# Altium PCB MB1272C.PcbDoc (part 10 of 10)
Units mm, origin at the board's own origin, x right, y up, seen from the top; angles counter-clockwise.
Board outline 101 x 71 mm, 6 copper layers (Top Layer, Signal Layer 1, Signal Layer 2, Signal Layer 3, Signal Layer 4, Bottom Layer), stack 1.552 mm thick; 520 components, 478 nets, 2156 pads, 1894 vias.
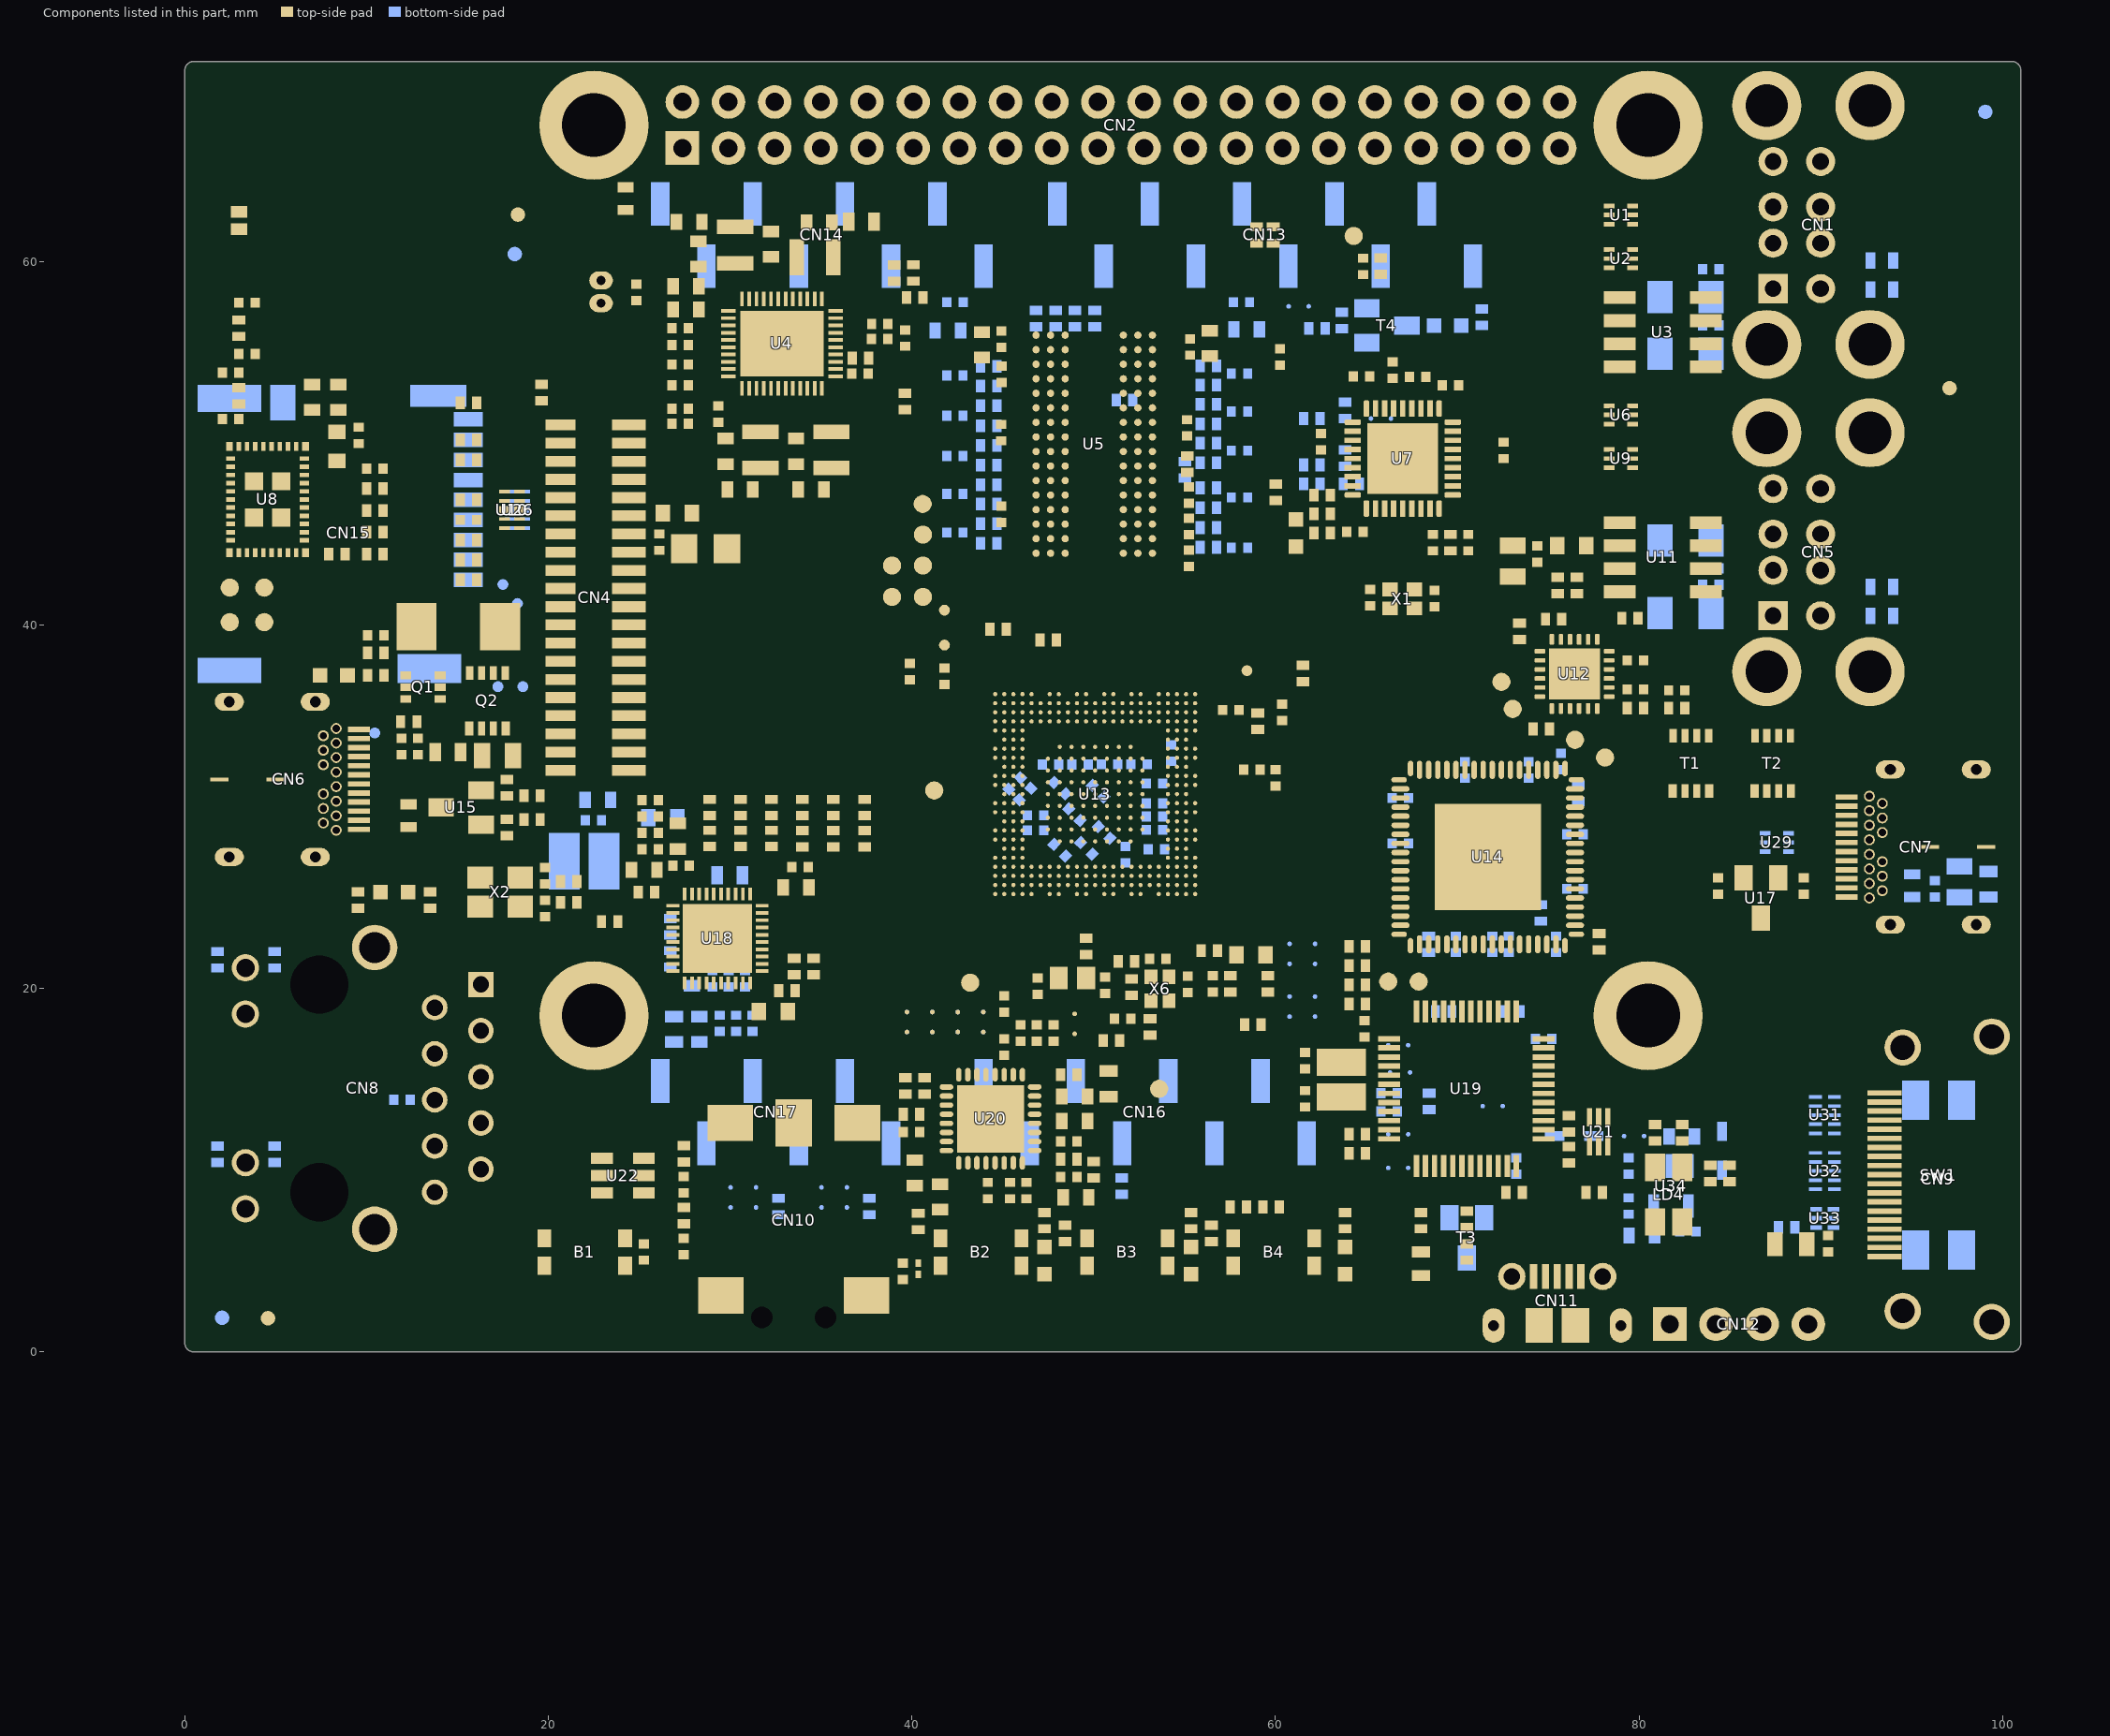
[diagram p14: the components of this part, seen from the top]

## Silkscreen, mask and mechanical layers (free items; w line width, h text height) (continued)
Drill Drawing:
  drawing of 549 lines, arcs and shapes, not listed
  text "PCB SPECIFICATIONS :" at 6.92,173.965 h3
  text "PCB : TYPE 4" at 155.276,173.613 h3
  text "MINIMUN PARAMETERS" at 192.17,173.59 h3
  text "A.   MATERIAL :" at 6.92,169.965 h3
  text "FR-4" at 45.42,169.965 h3
  text "TG-170" at 61.92,169.965 h3
  text "X  TG-150" at 80.17,169.965 h3
  text "TG-140" at 96.17,169.965 h3
  text "ASPECT-RATIO, AXE Z :" at 155.276,168.113 h3
  text "DEFAULT" at 192.17,168.09 h3
  text "B.   MATERIAL FAMILY :" at 6.92,166.965 h3
  text "N/A" at 45.42,166.965 h3
  text "C.   SOLDERMASK COLOR :" at 6.92,163.965 h3
  text "X  BLUE" at 45.42,163.965 h3
  text "WHITE" at 61.92,163.965 h3
  text "RED" at 80.17,163.965 h3
  text "BLACK" at 96.17,163.965 h3
  text "TRACKS : 0.090mm           / GAPS : 0.090mm" at 192.17,162.34 h3
  text "6:1 to 8:1 / LEVEL \"B\"" at 155.295,161.365 h3
  text "D.   SILKSCREEN COLOR :" at 6.92,160.965 h3
  text "X  WHITE" at 45.42,160.965 h3
  text "YELLOW" at 61.92,160.965 h3
  text "BLACK" at 80.17,160.965 h3
  text "Blue ink PANTONE 2955" at 96.17,160.965 h3
  text "MCU" at 192.495,158.265 h3
  text "E.   SURFACE FINISH :" at 6.92,157.965 h3
  text "X  ENIG" at 45.42,157.965 h3
  text "IMMERSION SILVER" at 61.92,157.965 h3
  text "IMMERSION TIN" at 96.17,157.965 h3
  text "HASL" at 45.42,154.965 h3
  text "HASL (PB-FREE)" at 61.92,154.965 h3
  text "GOLDEN FINGER" at 96.17,154.965 h3
  text "TRACKS : 0.090mm           / GAPS : 0.080mm" at 192.495,152.515 h3
  text "F.   IMPEDANCE CONTROL :" at 6.92,151.965 h3
  text "NO" at 45.42,151.965 h3
  text "X  YES  (SEE IMPEDANCE TABLE FOR DETAIL INFORMATION)" at 61.92,151.965 h3
  text "G.   THROUGH VIA :" at 6.92,148.965 h3
  text "PLUG THE VIAS WHICH ARE COVERED WITH SOLDERMASK ONE OR TWO SIDE." at 45.42,148.965 h3
  text "PLUG MATERIAL :" at 45.42,145.965 h3
  text "X  SOLDERMASK" at 70.92,145.965 h3
  text "NON-CONDUCTIVE EPOXY." at 96.17,145.965 h3
  text "H.   STACK-UP :" at 6.92,142.965 h3
  text "SEE LAYER STACK-UP SEQUENCE FOR OVERALL THICKNESS." at 45.42,142.965 h3
  text "Layer" at 157.322,132.1 h2
  text "Name" at 165.69,132.1 h2
  text "Material" at 181.866,132.1 h2
  text "Thickness" at 198.133,132.1 h2
  text "Constant" at 210.074,132.1 h2
  text "Board Layer Stack" at 221.128,132.1 h2
  text "IMPEDANCE TABLE     SDMMC1" at 63.325,131.975 h3
  text "IMPEDANCE TABLE     DDR" at -28.85,131.95 h3
  text "1" at 157.322,128.1 h2
  text "Top Overlay" at 165.69,128.1 h2
  text "LAYER" at -23.9,127 h3
  text "LAYER" at 67.575,126.975 h3
  text "TRACE" at 83.825,126.975 h3
  text "SPACING" at 94.325,126.975 h3
  text "IMPEDANCE" at 107.825,126.975 h3
  text "IMPEDANCE" at 124.825,126.975 h3
  text "TOL." at 143.575,126.975 h3
  text "TRACE" at -8.35,126.95 h3
  text "SPACING" at 2.15,126.95 h3
  text "IMPEDANCE" at 15.65,126.95 h3
  text "IMPEDANCE" at 32.65,126.95 h3
  text "TOL." at 51.4,126.95 h3
  text "(mm)" at 97.65,124.5 h2.5
  text "(mm)" at 5.475,124.475 h2.5
  text "(mm)" at 85.825,124.45 h2.5
  text "(mm)" at -6.35,124.425 h2.5
  text "(Single ended)" at 108.325,124.225 h2.5
  text "(Differential)" at 126.075,124.225 h2.5
  text "(Single ended)" at 16.15,124.2 h2.5
  text "(Differential)" at 33.9,124.2 h2.5
  text "2" at 157.322,124.1 h2
  text "Top Solder" at 165.69,124.1 h2
  text "Solder Resist" at 181.866,124.1 h2
  text "0,020mm" at 198.133,124.1 h2
  text "3,5" at 210.074,124.1 h2
  text "+/- 15%" at 142.63,120.585 h3
  text "0.130" at 84.8,120.5 h3
  text "0.120" at -7.375,120.475 h3
  text "0.260" at 96.825,120.475 h3
  text "0.300" at 4.65,120.45 h3
  text "+/- 10%" at 49.825,120.45 h3
  text "TOP/BOTTOM" at 63.805,120.46 h3
  text "50 ohm" at 111.18,120.41 h3
  text "55 ohm" at 19.005,120.385 h3
  text "NA" at 130.73,120.36 h3
  text "NA" at 38.555,120.335 h3
  text "3" at 157.322,120.1 h2
  text "Top Layer" at 165.69,120.1 h2
  text "Copper" at 181.866,120.1 h2
  text "0,035mm" at 198.133,120.1 h2
  text "TOP" at -22.075,118.825 h3
  text "+/- 15%" at 142.635,117.07 h3
  text "+/- 10%" at 49.85,117.05 h3
  text "NA" at 21.075,117 h3
  text "0.130" at 84.805,116.985 h3
  text "0.260" at 96.83,116.96 h3
  text "LAYER 2" at 67.25,116.925 h3
  text "100 ohm" at 35.05,116.9 h3
  text "50 ohm" at 111.185,116.895 h3
  text "NA" at 130.735,116.845 h3
  text "0.100/0.130/0.100" at -7.825,116.775 h3
  text "4" at 157.322,116.1 h2
  text "Dielectric 1" at 165.69,116.1 h2
  text "IT-180A 3313H" at 181.866,116.1 h2
  text "0,099mm" at 198.133,116.1 h2
  text "4,2" at 210.074,116.1 h2
  text "0.127" at -7.38,113.465 h3
  text "0.300" at 4.645,113.44 h3
  text "+/- 10%" at 49.82,113.44 h3
  text "55 ohm" at 19,113.375 h3
  text "NA" at 38.55,113.325 h3
  text "5" at 157.322,112.1 h2
  text "Signal Layer 1" at 165.69,112.1 h2
  text "Copper" at 181.866,112.1 h2
  text "0,035mm" at 198.133,112.1 h2
  text "LAYER 2" at -25.2,111.825 h3
  text "+/- 10%" at 49.845,110.04 h3
  text "NA" at 21.07,109.99 h3
  text "100 ohm" at 35.045,109.89 h3
  text "IMPEDANCE TABLE     USB" at 63.175,109.875 h3
  text "0.090/0.140/0.090" at -7.83,109.765 h3
  text "6" at 157.322,108.1 h2
  text "Dielectric 2" at 165.69,108.1 h2
  text "IT-180A" at 181.866,108.1 h2
  text "0,130mm" at 198.133,108.1 h2
  text "4,2" at 210.074,108.1 h2
  text "0.120" at -7.38,106.44 h3
  text "0.300" at 4.645,106.415 h3
  text "+/- 10%" at 49.82,106.415 h3
  text "55 ohm" at 19,106.35 h3
  text "NA" at 38.55,106.3 h3
  text "LAYER" at 67.425,104.875 h3
  text "TRACE" at 83.675,104.875 h3
  text "SPACING" at 94.175,104.875 h3
  text "IMPEDANCE" at 107.675,104.875 h3
  text "IMPEDANCE" at 124.675,104.875 h3
  text "TOL." at 143.425,104.875 h3
  text "BOTTOM" at -24.775,104.75 h3
  text "7" at 157.322,104.1 h2
  text "Signal Layer 2" at 165.69,104.1 h2
  text "Copper" at 181.866,104.1 h2
  text "0,035mm" at 198.133,104.1 h2
  text "+/- 10%" at 49.845,103.015 h3
  text "NA" at 21.07,102.965 h3
  text "100 ohm" at 35.045,102.865 h3
  text "0.100/0.130/0.100" at -7.83,102.74 h3
  text "(mm)" at 97.5,102.4 h2.5
  text "(mm)" at 85.675,102.35 h2.5
  text "(Single ended)" at 108.175,102.125 h2.5
  text "(Differential)" at 125.925,102.125 h2.5
  text "8" at 157.322,100.1 h2
  text "Dielectric 3" at 165.69,100.1 h2
  text "IT-180A 1080*2" at 181.866,100.1 h2
  text "0,885mm" at 198.133,100.1 h2
  text "4,25" at 210.074,100.1 h2
  text "0.100" at 84.65,98.4 h3
  text "NA" at 113.275,98.4 h3
  text "0.090" at 96.675,98.375 h3
  text "90 ohm" at 127.925,98.375 h3
  text "+/- 15%" at 141.925,98.375 h3
  text "TOP/BOTTOM" at 63.655,98.36 h3
  text "9" at 157.322,96.1 h2
  text "Signal Layer 3" at 165.69,96.1 h2
  text "Copper" at 181.866,96.1 h2
  text "0,035mm" at 198.133,96.1 h2
  text "IMPEDANCE TABLE     DSI" at 63.175,92.475 h3
  text "10" at 157.322,92.1 h2
  text "Dielectric 4" at 165.69,92.1 h2
  text "IT-180A" at 181.866,92.1 h2
  text "0,130mm" at 198.133,92.1 h2
  text "4,2" at 210.074,92.1 h2
  text "11" at 157.322,88.1 h2
  text "Signal Layer 4" at 165.69,88.1 h2
  text "Copper" at 181.866,88.1 h2
  text "0,035mm" at 198.133,88.1 h2
  text "LAYER" at 67.425,87.475 h3
  text "TRACE" at 83.675,87.475 h3
  text "SPACING" at 94.175,87.475 h3
  text "IMPEDANCE" at 107.675,87.475 h3
  text "IMPEDANCE" at 124.675,87.475 h3
  text "TOL." at 143.425,87.475 h3
  text "(mm)" at 97.5,85 h2.5
  text "(mm)" at 85.675,84.95 h2.5
  text "(Single ended)" at 108.175,84.725 h2.5
  text "(Differential)" at 125.925,84.725 h2.5
  text "12" at 157.322,84.1 h2
  text "Dielectric 5" at 165.69,84.1 h2
  text "IT-180A 3313H" at 181.866,84.1 h2
  text "0,099mm" at 198.133,84.1 h2
  text "4,2" at 210.074,84.1 h2
  text "0.100" at 84.65,81 h3
  text "NA" at 113.275,81 h3
  text "0.130" at 96.675,80.975 h3
  text "100 ohm" at 127.925,80.975 h3
  text "+/- 15%" at 141.925,80.975 h3
  text "TOP/BOTTOM" at 63.655,80.96 h3
  text "13" at 157.322,80.1 h2
  text "Bottom Layer" at 165.69,80.1 h2
  text "Copper" at 181.866,80.1 h2
  text "0,035mm" at 198.133,80.1 h2
  text "14" at 157.322,76.1 h2
  text "Bottom Solder" at 165.69,76.1 h2
  text "Solder Resist" at 181.866,76.1 h2
  text "0,020mm" at 198.133,76.1 h2
  text "3,5" at 210.074,76.1 h2
  text "15" at 157.322,72.1 h2
  text "Bottom Overlay" at 165.69,72.1 h2
  text "Symbol" at 114.772,63.867 h2.4
  text "Count" at 124.175,63.867 h2.4
  text "Hole Size" at 134.939,63.867 h2.4
  text "Plated" at 154.189,63.867 h2.4
  text "Hole Type" at 162.444,63.867 h2.4
  text "Drill Layer Pair" at 174.458,63.867 h2.4
  text "Hole Length" at 197.658,63.867 h2.4
  text "Routed Path Length" at 215.794,63.867 h2.4
  text "530" at 124.175,59.722 h2
  text "0,100mm (3,94mil)" at 134.939,59.722 h2
  text "PTH" at 154.189,59.722 h2
  text "Round" at 162.444,59.722 h2
  text "Top Layer - Signal Layer 1" at 174.458,59.722 h2
  text "-" at 197.658,59.722 h2
  text "-" at 215.794,59.722 h2
  text "O" at 113.984,59.468 h1.84
  text "912" at 124.175,55.577 h2
  text "0,200mm (7,87mil)" at 134.939,55.577 h2
  text "PTH" at 154.189,55.577 h2
  text "Round" at 162.444,55.577 h2
  text "Top Layer - Bottom Layer" at 174.458,55.577 h2
  text "-" at 197.658,55.577 h2
  text "-" at 215.794,55.577 h2
  text "452" at 124.175,51.431 h2
  text "0,300mm (11,81mil)" at 134.939,51.431 h2
  text "PTH" at 154.189,51.431 h2
  text "Round" at 162.444,51.431 h2
  text "Top Layer - Bottom Layer" at 174.458,51.431 h2
  text "-" at 197.658,51.431 h2
  text "-" at 215.794,51.431 h2
  text "28" at 124.175,47.286 h2
  text "0,400mm (15,75mil)" at 134.939,47.286 h2
  text "PTH" at 154.189,47.286 h2
  text "Round" at 162.444,47.286 h2
  text "Top Layer - Bottom Layer" at 174.458,47.286 h2
  text "-" at 197.658,47.286 h2
  text "-" at 215.794,47.286 h2
  text "I" at 114.291,47.032 h1.84
  text "2" at 124.175,43.141 h2
  text "0,500mm (19,69mil)" at 134.939,43.141 h2
  text "PTH" at 154.189,43.141 h2
  text "Round" at 162.444,43.141 h2
  text "Top Layer - Bottom Layer" at 174.458,43.141 h2
  text "-" at 197.658,43.141 h2
  text "-" at 215.794,43.141 h2
  text "J" at 113.984,42.887 h1.84
  text "8" at 124.175,38.996 h2
  text "0,600mm (23,62mil)" at 134.939,38.996 h2
  text "PTH" at 154.189,38.996 h2
  text "Slot" at 162.444,38.996 h2
  text "Top Layer - Bottom Layer" at 174.458,38.996 h2
  text "1,200mm (47,24mil)" at 197.658,38.996 h2
  text "0,600mm (23,62mil)" at 215.794,38.996 h2
  text "H" at 113.984,38.742 h1.84
  text "2" at 124.175,34.85 h2
  text "0,600mm (23,62mil)" at 134.939,34.85 h2
  text "PTH" at 154.189,34.85 h2
  text "Slot" at 162.444,34.85 h2
  text "Top Layer - Bottom Layer" at 174.458,34.85 h2
  text "1,300mm (51,18mil)" at 197.658,34.85 h2
  text "0,700mm (27,56mil)" at 215.794,34.85 h2
  text "A" at 113.984,34.597 h1.84
  text "12" at 124.175,30.705 h2
  text "0,900mm (35,43mil)" at 134.939,30.705 h2
  text "PTH" at 154.189,30.705 h2
  text "Round" at 162.444,30.705 h2
  text "Top Layer - Bottom Layer" at 174.458,30.705 h2
  text "-" at 197.658,30.705 h2
  text "-" at 215.794,30.705 h2
  text "16" at 124.175,26.56 h2
  text "0,920mm (36,22mil)" at 134.939,26.56 h2
  text "PTH" at 154.189,26.56 h2
  text "Round" at 162.444,26.56 h2
  text "Top Layer - Bottom Layer" at 174.458,26.56 h2
  text "-" at 197.658,26.56 h2
  text "-" at 215.794,26.56 h2
  text "F" at 113.984,26.306 h1.84
  text "48" at 124.175,22.414 h2
  text "1,000mm (39,37mil)" at 134.939,22.414 h2
  text "PTH" at 154.189,22.414 h2
  text "Round" at 162.444,22.414 h2
  text "Top Layer - Bottom Layer" at 174.458,22.414 h2
  text "-" at 197.658,22.414 h2
  text "-" at 215.794,22.414 h2
  text "2" at 124.175,18.269 h2
  text "1,200mm (47,24mil)" at 134.939,18.269 h2
  text "NPTH" at 154.189,18.269 h2
  text "Round" at 162.444,18.269 h2
  text "Top Layer - Bottom Layer" at 174.458,18.269 h2
  text "-" at 197.658,18.269 h2
  text "-" at 215.794,18.269 h2
  text "4" at 124.175,14.124 h2
  text "1,350mm (53,15mil)" at 134.939,14.124 h2
  text "PTH" at 154.189,14.124 h2
  text "Round" at 162.444,14.124 h2
  text "Top Layer - Bottom Layer" at 174.458,14.124 h2
  text "-" at 197.658,14.124 h2
  text "-" at 215.794,14.124 h2
  text "K" at 113.984,13.87 h1.84
  text "2" at 124.175,9.979 h2
  text "1,700mm (66,93mil)" at 134.939,9.979 h2
  text "PTH" at 154.189,9.979 h2
  text "Round" at 162.444,9.979 h2
  text "Top Layer - Bottom Layer" at 174.458,9.979 h2
  text "-" at 197.658,9.979 h2
  text "-" at 215.794,9.979 h2
  text "L" at 113.984,9.725 h1.84
  text "8" at 124.175,5.833 h2
  text "2,330mm (91,73mil)" at 134.939,5.833 h2
  text "PTH" at 154.189,5.833 h2
  text "Round" at 162.444,5.833 h2
  text "Top Layer - Bottom Layer" at 174.458,5.833 h2
  text "-" at 197.658,5.833 h2
  text "-" at 215.794,5.833 h2
  text "G" at 113.984,5.58 h1.84
  text "2" at 124.175,1.688 h2
  text "3,200mm (125,98mil)" at 134.939,1.688 h2
  text "NPTH" at 154.189,1.688 h2
  text "Round" at 162.444,1.688 h2
  text "Top Layer - Bottom Layer" at 174.458,1.688 h2
  text "-" at 197.658,1.688 h2
  text "-" at 215.794,1.688 h2
  text "M" at 113.984,1.434 h1.84
  text "4" at 124.175,-2.457 h2
  text "3,500mm (137,80mil)" at 134.939,-2.457 h2
  text "PTH" at 154.189,-2.457 h2
  text "Round" at 162.444,-2.457 h2
  text "Top Layer - Bottom Layer" at 174.458,-2.457 h2
  text "-" at 197.658,-2.457 h2
  text "-" at 215.794,-2.457 h2
  text "N" at 113.984,-2.711 h1.84
  text "2032 Total" at 124.175,-6.602 h2
  text "Slot definitions :" at 114.772,-9.504 h2
  text "Routed Path Length" at 128.413,-9.504 h2
  text "= Calculated from tool start centre position to tool end centre position." at 145.309,-9.504 h2
  text "Hole Length" at 128.413,-11.162 h2
  text "= Routed Path Length + Tool Size = Slot length as defined in the PCB layout" at 139.037,-11.162 h2
  text ".Layer_Name" at 14.068,-11.217 h3
  text ".DRL" at 55.763,-11.217 h3
M20-Top Sheet Box:
  circle w0.254: c92.072,-17.938 r1.3
  region: 77.594,-19.031 66.838,-19.031 67.832,-16.538 75.689,-16.538 76.138,-15.779 78.347,-18.327
  region: 91.598,-10.701 76.07,-10.701 75.376,-12.477 74.165,-13.702 72.768,-11.842 72.768,-10.191 73.911,-8.794 75.347,-8.415 91.598,-8.415
  lines w0.254: 67.832,-16.538 76.624,-16.538 73.557,-13 cw(c75.361,-11.056) 75.601,-8.415 92.365,-8.415 91.603,-10.701 ; 71.145,-8.168 cw(c73.572,-9.139) 73.808,-6.536 ; 71.185,-8.136 66.838,-19.031 86.161,-19.031 ccw(c86.41,-16.296) 88.959,-17.316 ; 72.924,-12.07 78.347,-18.327 ; 73.178,-12.07 78.483,-18.192 ; 73.178,-11.816 78.483,-17.938 ; 73.276,-10.701 86.269,-10.701 ; 73.305,-11.689 78.61,-17.811 ; 73.432,-11.562 78.737,-17.684 ; 73.559,-11.435 78.864,-17.557 ; 73.686,-11.308 78.991,-17.43 ; 73.741,-9.356 79.046,-15.477 ; 73.809,-6.536 93.259,-6.536 88.96,-17.314 ; 73.813,-11.181 79.064,-17.24 ; 73.813,-10.927 79.118,-17.049 ; 73.813,-10.673 79.118,-16.795 ; 73.813,-9.784 79.118,-15.906 ; 73.94,-10.546 79.245,-16.668 ; 73.94,-10.165 79.245,-16.287 ; 75.312,-16.551 ccw(c75.417,-16.016) 75.715,-15.559 ; 76.399,-10.688 ccw(c76.373,-11.255) 76.042,-11.717 78.407,-14.446 cw(c76.603,-16.39) 77.336,-18.939 ; 82.68,-18.827 85.569,-10.447 ; 82.902,-18.777 85.771,-10.456 ; 83.029,-18.777 85.898,-10.456 ; 83.283,-18.777 86.152,-10.456 ; 83.537,-18.777 86.406,-10.456 ; 83.791,-18.777 86.66,-10.456 ; 84.045,-18.777 86.914,-10.456 ; 84.299,-18.777 87.168,-10.456 ; 84.553,-18.777 87.422,-10.456 ; 84.807,-18.777 87.676,-10.456 ; 85.016,-18.827 87.905,-10.447 ; 87.905,-10.701 91.598,-10.701 ; 90.929,-10.699 91.691,-8.413 ; 91.095,-10.701 91.857,-8.415 ; 91.349,-10.701 92.111,-8.415
  lines w0.3: 5.068,-22.917 95.068,-22.917 95.068,-2.917 5.068,-2.917 ; 5.068,-17.917 65.068,-17.917 ; 5.068,-12.917 65.068,-12.917 ; 5.068,-7.917 65.068,-7.917 ; 5.068,-22.917 5.068,-2.917 ; 45.068,-22.917 45.068,-7.917 ; 65.068,-22.917 65.068,-2.917 ; 82.68,-18.827 85.016,-18.827
  text "Project: '.Board_Name'" at 6.068,-6.133 h3
  text "Layer:" at 6.068,-11.217 h3
  text "Gerber:" at 46.057,-11.217 h3
  text "Variant: '.VariantName'" at 6.068,-16.217 h3
  text "Ref: MB1272" at 46.184,-16.217 h3
  text "R" at 91.564,-18.7 h1.52
  text "Date: 18-SEPT-26" at 6.068,-21.217 h3
  text "Rev: '.Board_PCB_Revision'" at 46.127,-21.217 h3
M21-Bottom Sheet Box:
  circle w0.254: c8.251,-17.938 r1.3
  region: 8.726,-10.701 24.253,-10.701 24.947,-12.477 26.158,-13.702 27.555,-11.842 27.555,-10.191 26.412,-8.794 24.976,-8.415 8.726,-8.415
  region: 22.729,-19.031 33.485,-19.031 32.492,-16.538 24.634,-16.538 24.185,-15.779 21.977,-18.327
  lines w0.254: 8.212,-8.415 8.974,-10.701 ; 8.466,-8.415 9.228,-10.701 ; 8.632,-8.413 9.394,-10.699 ; 8.72,-10.701 7.958,-8.415 24.722,-8.415 cw(c24.962,-11.056) 26.766,-13 23.7,-16.538 32.492,-16.538 ; 8.726,-10.701 12.418,-10.701 ; 11.363,-17.314 7.064,-6.536 26.514,-6.536 ; 11.364,-17.316 ccw(c13.914,-16.296) 14.162,-19.031 33.485,-19.031 29.139,-8.136 ; 12.418,-10.447 15.307,-18.827 ; 12.647,-10.456 15.516,-18.777 ; 12.901,-10.456 15.77,-18.777 ; 13.155,-10.456 16.024,-18.777 ; 13.409,-10.456 16.278,-18.777 ; 13.663,-10.456 16.532,-18.777 ; 13.917,-10.456 16.786,-18.777 ; 14.054,-10.701 27.047,-10.701 ; 14.171,-10.456 17.04,-18.777 ; 14.425,-10.456 17.294,-18.777 ; 14.552,-10.456 17.421,-18.777 ; 14.754,-10.447 17.643,-18.827 ; 21.078,-16.668 26.383,-10.546 ; 21.078,-16.287 26.383,-10.165 ; 21.205,-17.049 26.51,-10.927 ; 21.205,-16.795 26.51,-10.673 ; 21.205,-15.906 26.51,-9.784 ; 21.259,-17.24 26.51,-11.181 ; 21.277,-15.477 26.582,-9.356 ; 21.332,-17.43 26.637,-11.308 ; 21.459,-17.557 26.764,-11.435 ; 21.586,-17.684 26.891,-11.562 ; 21.713,-17.811 27.018,-11.689 ; 21.84,-18.192 27.145,-12.07 ; 21.84,-17.938 27.145,-11.816 ; 21.977,-18.327 27.399,-12.07 ; 22.987,-18.939 cw(c23.72,-16.39) 21.916,-14.446 24.281,-11.717 ccw(c23.951,-11.255) 23.925,-10.688 ; 24.608,-15.559 ccw(c24.906,-16.016) 25.011,-16.551 ; 26.515,-6.536 cw(c26.752,-9.139) 29.178,-8.168
  lines w0.3: 15.307,-18.827 17.643,-18.827 ; 35.068,-22.917 35.068,-2.917 ; 35.068,-17.917 95.068,-17.917 ; 35.068,-12.917 95.068,-12.917 ; 35.068,-7.917 95.068,-7.917 ; 55.068,-22.917 55.068,-7.917 ; 5.068,-22.917 5.068,-2.917 95.068,-2.917 95.068,-22.917 5.068,-22.917
  text "Project: '.Board_Name'" at 93.874,-6.133 h3
  text "Gerber:" at 53.885,-11.217 h3
  text "Layer:" at 93.874,-11.217 h3
  text "Ref: MB1272" at 53.885,-16.217 h3
  text "Variant: '.VariantName'" at 93.874,-16.217 h3
  text "R" at 8.759,-18.7 h1.52
  text "Rev: '.Board_PCB_Revision'" at 53.942,-21.217 h3
  text "Date: 18-SEPT-26" at 93.874,-21.217 h3

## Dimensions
0,70.5 to 101,70.5 on M2-Board Dimensions
0.5,71 to 0.5,0 on M2-Board Dimensions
